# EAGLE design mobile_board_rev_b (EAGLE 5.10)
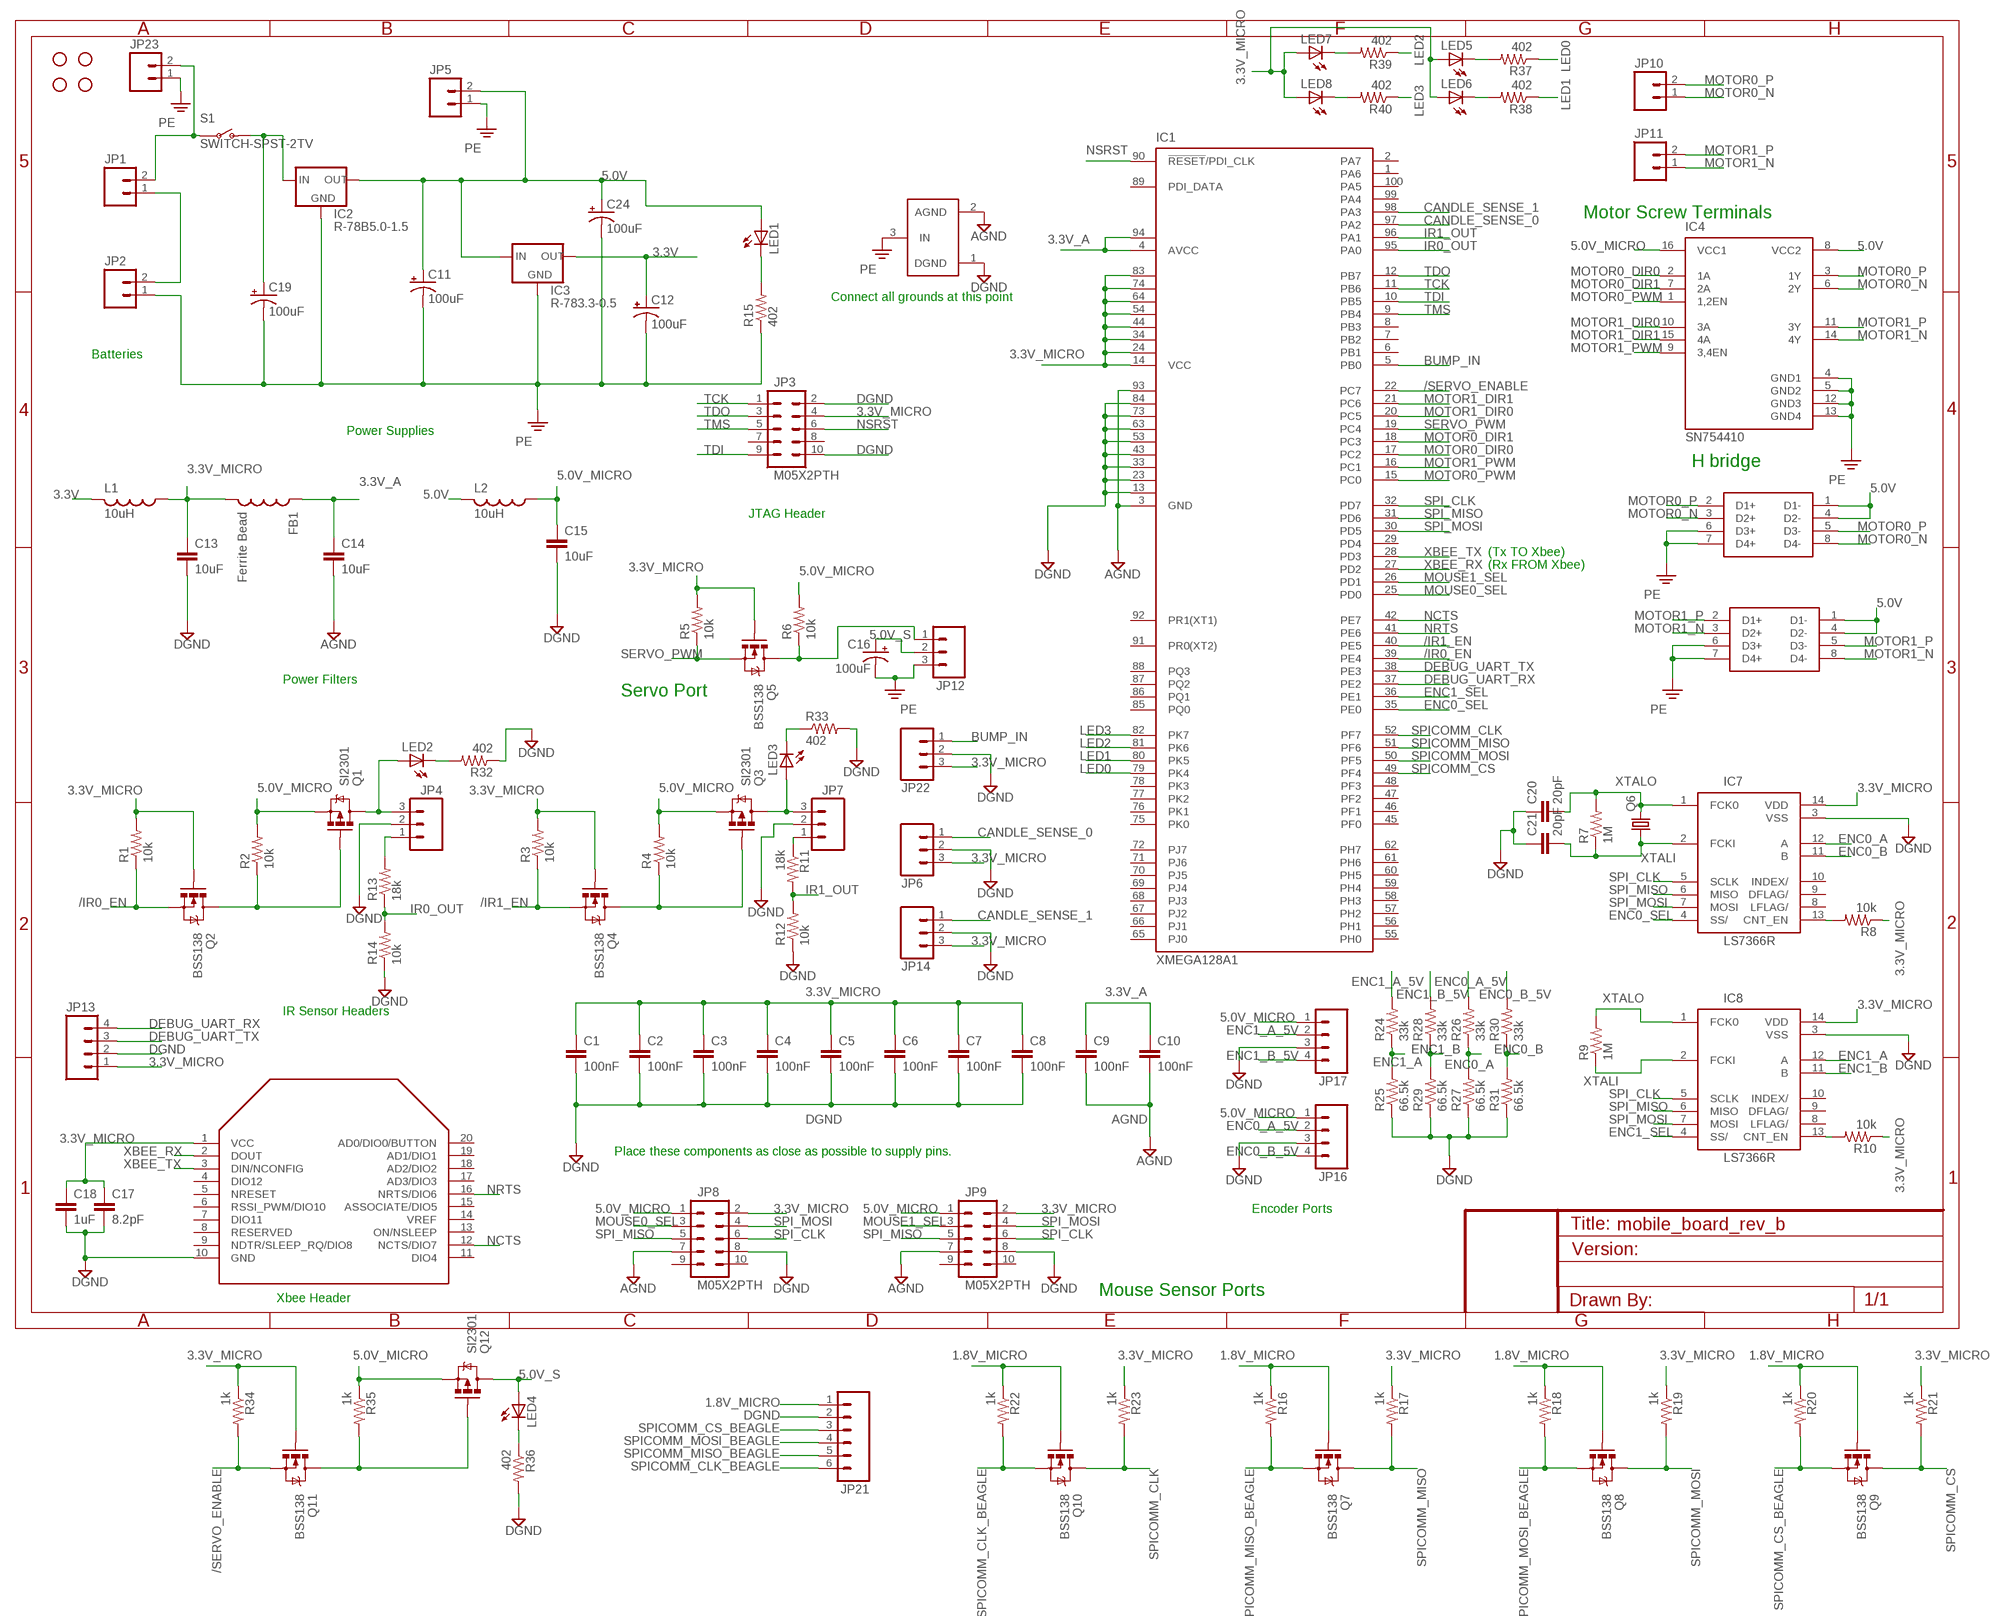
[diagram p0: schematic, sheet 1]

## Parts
C1  100nF  C-EUC0402  [C0402]
C2  100nF  C-EUC0402  [C0402]
C3  100nF  C-EUC0402  [C0402]
C4  100nF  C-EUC0402  [C0402]
C5  100nF  C-EUC0402  [C0402]
C6  100nF  C-EUC0402  [C0402]
C7  100nF  C-EUC0402  [C0402]
C8  100nF  C-EUC0402  [C0402]
C9  100nF  C-EUC0402  [C0402]
C10  100nF  C-EUC0402  [C0402]
C11  100uF  CPOL-USC  [PANASONIC_C]
C12  100uF  CPOL-USC  [PANASONIC_C]
C13  10uF  C-EUC1210  [C1210]
C14  10uF  C-EUC1210  [C1210]
C15  10uF  C-EUC1210  [C1210]
C16  100uF  CPOL-USC  [PANASONIC_C]
C17  8.2pF  C-EUC0805  [C0805]
C18  1uF  C-EUC0805  [C0805]
C19  100uF  CPOL-USC  [PANASONIC_C]
C20  20pF  C-EUC0402  [C0402]
C21  20pF  C-EUC0402  [C0402]
C24  100uF  CPOL-USC  [PANASONIC_C]
FB1  Ferrite Bead  INDUCTOR1210  [1210]
IC1  XMEGA128A1  [TQFP100]
IC2  R-78B5.0-1.5  78XXS  [78XXS]
IC3  R-783.3-0.5  78XXS  [78XXS]
IC4  SN754410  [16_DIP]
IC5  UC3611N  [8_DIP]
IC6  UC3611N  [8_DIP]
IC7  LS7366R  [SOIC_14]
IC8  LS7366R  [SOIC_14]
IC9  XBEE_ZIGBEE  [XBEE]
JP1  M02-JST-2MM-SMT  [S2B-PH]
JP2  M02-JST-2MM-SMT  [S2B-PH]
JP3  M05X2PTH  [AVR_ICSP]
JP4  M03PTH  [1X03]
JP5  M02-JST-2MM-SMT  [S2B-PH]
JP6  M03PTH  [1X03]
JP7  M03PTH  [1X03]
JP8  M05X2PTH  [AVR_ICSP]
JP9  M05X2PTH  [AVR_ICSP]
JP10  M02-JST-2MM-SMT  [S2B-PH]
JP11  M02-JST-2MM-SMT  [S2B-PH]
JP12  M03PTH  [1X03]
JP13  M04PTH  [1X04]
JP14  M03PTH  [1X03]
JP15  STAND-OFF  [STAND-OFF]
JP16  M04PTH  [1X04]
JP17  M04PTH  [1X04]
JP18  STAND-OFF  [STAND-OFF]
JP19  STAND-OFF  [STAND-OFF]
JP20  STAND-OFF  [STAND-OFF]
JP21  M06SIP  [1X06]
JP22  M03PTH  [1X03]
JP23  M02PTH  [1X02]
L1  10uH  L-USL1812  [L1812]
L2  10uH  L-USL1812  [L1812]
LED1  LED1206  [LED-1206]
LED2  LED1206  [LED-1206]
LED3  LED1206  [LED-1206]
LED4  LED1206  [LED-1206]
LED5  LED1206  [LED-1206]
LED6  LED1206  [LED-1206]
LED7  LED1206  [LED-1206]
LED8  LED1206  [LED-1206]
Q1  SI2301  MOSFET-PCHANNEL  [SOT23]
Q2  BSS138  MOSFET-NCHANNELSMD  [SOT23-3]
Q3  SI2301  MOSFET-PCHANNEL  [SOT23]
Q4  BSS138  MOSFET-NCHANNELSMD  [SOT23-3]
Q5  BSS138  MOSFET-NCHANNELSMD  [SOT23-3]
Q6  CRYSTALHC49US  [HC49US]
Q7  BSS138  MOSFET-NCHANNELSMD  [SOT23-3]
Q8  BSS138  MOSFET-NCHANNELSMD  [SOT23-3]
Q9  BSS138  MOSFET-NCHANNELSMD  [SOT23-3]
Q10  BSS138  MOSFET-NCHANNELSMD  [SOT23-3]
Q11  BSS138  MOSFET-NCHANNELSMD  [SOT23-3]
Q12  SI2301  MOSFET-PCHANNEL  [SOT23]
R1  10k  R-US_R0805  [R0805]
R2  10k  R-US_R0805  [R0805]
R3  10k  R-US_R0805  [R0805]
R4  10k  R-US_R0805  [R0805]
R5  10k  R-US_R0805  [R0805]
R6  10k  R-US_R0805  [R0805]
R7  1M  R-US_R0402  [R0402]
R8  10k  R-US_R0402  [R0402]
R9  1M  R-US_R0402  [R0402]
R10  10k  R-US_R0402  [R0402]
R11  18k  R-US_R0805  [R0805]
R12  10k  R-US_R0805  [R0805]
R13  18k  R-US_R0805  [R0805]
R14  10k  R-US_R0805  [R0805]
R15  402  R-US_R0805  [R0805]
R16  1k  R-US_R0402  [R0402]
R17  1k  R-US_R0402  [R0402]
R18  1k  R-US_R0402  [R0402]
R19  1k  R-US_R0402  [R0402]
R20  1k  R-US_R0402  [R0402]
R21  1k  R-US_R0402  [R0402]
R22  1k  R-US_R0402  [R0402]
R23  1k  R-US_R0402  [R0402]
R24  33k  R-US_R0402  [R0402]
R25  66.5k  R-US_R0402  [R0402]
R26  33k  R-US_R0402  [R0402]
R27  66.5k  R-US_R0402  [R0402]
R28  33k  R-US_R0402  [R0402]
R29  66.5k  R-US_R0402  [R0402]
R30  33k  R-US_R0402  [R0402]
R31  66.5k  R-US_R0402  [R0402]
R32  402  R-US_R0805  [R0805]
R33  402  R-US_R0805  [R0805]
R34  1k  R-US_R0402  [R0402]
R35  1k  R-US_R0402  [R0402]
R36  402  R-US_R0805  [R0805]
R37  402  R-US_R0805  [R0805]
R38  402  R-US_R0805  [R0805]
R39  402  R-US_R0805  [R0805]
R40  402  R-US_R0805  [R0805]
S1  SWITCH-SPST-2TV  [SWITCH-SPST-VERTICAL]
U$1  GND_CONNECT  [GND_CONNECT]

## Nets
1.8V_MICRO: JP21.1 Q7.1(G) Q8.1(G) Q9.1(G) Q10.1(G) R16.1 R18.1 R20.1 R22.1
3.3V: C12.+ IC3.OUT L1.2
3.3V_A: C9.1 C10.1 C14.1 FB1.1 IC1.4(AVCC) IC1.94(AVCC1)
3.3V_MICRO: C1.1 C2.1 C3.1 C4.1 C5.1 C6.1 C7.1 C8.1 C13.1 C17.1 C18.1 FB1.2 IC1.14(VCC) IC1.24(VCC1) IC1.34(VCC2) IC1.44(VCC3) IC1.54(VCC4) IC1.64(VCC5) IC1.74(VCC6) IC1.83(VCC7) IC7.14(VDD) IC8.14(VDD) IC9.1(VCC) JP3.4 JP6.3 JP8.2 JP9.2 JP13.1 JP14.3 JP22.3 L1.1 LED5.A LED6.A LED7.A LED8.A Q2.1(G) Q4.1(G) Q5.1(G) Q11.1(G) R1.2 R3.2 R5.2 R8.1 R10.1 R17.1 R19.1 R21.1 R23.1 R34.1
5.0V: C11.+ C24.+ IC2.OUT IC3.IN IC4.8(VCC2) IC5.1(D1-) IC5.4(D2-) IC6.1(D1-) IC6.4(D2-) JP5.2 L2.2 LED1.A
5.0V_MICRO: C15.1 IC4.16(VCC1) JP8.1 JP9.1 JP16.1 JP17.1 L2.1 Q1.2(S) Q3.2(S) Q12.2(S) R2.2 R4.2 R6.2 R35.1
5.0V_S: C16.+ JP12.2 LED4.A Q12.3(D)
/IR0_EN: IC1.39(PE4) Q2.2(S) R1.1
/IR1_EN: IC1.40(PE5) Q4.2(S) R3.1
/SERVO_ENABLE: IC1.22(PC7) Q11.2(S) R34.2
AGND: C9.2 C10.2 C14.2 IC1.3(GND) IC1.93(GND9) JP8.7 JP9.7 U$1.2(AGND)
BUMP_IN: IC1.5(PB0) JP22.1
CANDLE_SENSE_0: IC1.97(PA2) JP6.1
CANDLE_SENSE_1: IC1.98(PA3) JP14.1
DEBUG_UART_RX: IC1.37(PE2) JP13.4
DEBUG_UART_TX: IC1.38(PE3) JP13.3
DGND: C1.2 C2.2 C3.2 C4.2 C5.2 C6.2 C7.2 C8.2 C13.2 C15.2 C17.2 C18.2 C20.1 C21.1 IC1.13(GND1) IC1.23(GND2) IC1.33(GND3) IC1.43(GND4) IC1.53(GND5) IC1.63(GND6) IC1.73(GND7) IC1.84(GND8) IC7.3(VSS) IC8.3(VSS) IC9.10(GND) JP3.2 JP3.10 JP4.2 JP6.2 JP7.2 JP8.8 JP9.8 JP13.2 JP14.2 JP16.3 JP17.3 JP21.2 JP22.2 R12.1 R14.1 R25.1 R27.1 R29.1 R31.1 R32.1 R33.2 R36.2 U$1.1(DGND)
ENC0_A: IC7.12(A) R26.1 R27.2
ENC0_A_5V: JP16.2 R26.2
ENC0_B: IC7.11(B) R30.1 R31.2
ENC0_B_5V: JP16.4 R30.2
ENC0_SEL: IC1.35(PE0) IC7.4(SS/)
ENC1_A: IC8.12(A) R24.1 R25.2
ENC1_A_5V: JP17.2 R24.2
ENC1_B: IC8.11(B) R28.1 R29.2
ENC1_B_5V: JP17.4 R28.2
ENC1_SEL: IC1.36(PE1) IC8.4(SS/)
IR0_OUT: IC1.95(PA0) R13.1 R14.2
IR1_OUT: IC1.96(PA1) R11.2 R12.2
LED0: IC1.79(PK4) R37.1
LED1: IC1.80(PK5) R38.1
LED2: IC1.81(PK6) R39.1
LED3: IC1.82(PK7) R40.1
MOTOR0_DIR0: IC1.17(PC2) IC4.2(1A)
MOTOR0_DIR1: IC1.18(PC3) IC4.7(2A)
MOTOR0_N: IC4.6(2Y) IC5.3(D2+) IC5.8(D4-) JP10.1
MOTOR0_P: IC4.3(1Y) IC5.2(D1+) IC5.5(D3-) JP10.2
MOTOR0_PWM: IC1.15(PC0) IC4.1(1,2EN)
MOTOR1_DIR0: IC1.20(PC5) IC4.10(3A)
MOTOR1_DIR1: IC1.21(PC6) IC4.15(4A)
MOTOR1_N: IC4.14(4Y) IC6.3(D2+) IC6.8(D4-) JP11.1
MOTOR1_P: IC4.11(3Y) IC6.2(D1+) IC6.5(D3-) JP11.2
MOTOR1_PWM: IC1.16(PC1) IC4.9(3,4EN)
MOUSE0_SEL: IC1.25(PD0) JP8.3
MOUSE1_SEL: IC1.26(PD1) JP9.3
N$1: JP1.1 JP2.2
N$2: C19.+ IC2.IN S1.1(O)
N$3: LED1.C R15.2
N$4: JP7.3 LED3.A Q3.3(D)
N$5: Q3.1(G) Q4.3(D) R4.1
N$6: LED2.C R32.2
N$7: JP1.2 JP23.2 S1.2(P)
N$8: JP4.3 LED2.A Q1.3(D)
N$9: Q1.1(G) Q2.3(D) R2.1
N$10: LED3.C R33.1
N$11: JP12.1 Q5.3(D) R6.1
N$12: IC7.13(CNT_EN) R8.2
N$13: LED4.C R36.1
N$14: Q11.3(D) Q12.1(G) R35.2
N$15: IC8.13(CNT_EN) R10.2
N$16: JP7.1 R11.1
N$18: JP4.1 R13.2
N$20: LED8.C R40.2
N$21: LED7.C R39.2
N$22: LED5.C R37.2
N$23: LED6.C R38.2
NCTS: IC1.42(PE7) IC9.12(NCTS/DIO7)
NRTS: IC1.41(PE6) IC9.16(NRTS/DIO6)
NSRST: IC1.90(!RESET!/PDI_CLK) JP3.6
PE: C11.- C12.- C16.- C19.- C24.- IC2.GND IC3.GND IC4.4(GND1) IC4.5(GND2) IC4.12(GND3) IC4.13(GND4) IC5.6(D3+) IC5.7(D4+) IC6.6(D3+) IC6.7(D4+) JP2.1 JP5.1 JP12.3 JP23.1 R15.1 U$1.3(IN)
SERVO_PWM: IC1.19(PC4) Q5.2(S) R5.1
SPI_CLK: IC1.32(PD7) IC7.5(SCLK) IC8.5(SCLK) JP8.6 JP9.6
SPI_MISO: IC1.31(PD6) IC7.6(MISO) IC8.6(MISO) JP8.5 JP9.5
SPI_MOSI: IC1.30(PD5) IC7.7(MOSI) IC8.7(MOSI) JP8.4 JP9.4
SPICOMM_CLK: IC1.52(PF7) Q10.3(D) R23.2
SPICOMM_CLK_BEAGLE: JP21.6 Q10.2(S) R22.2
SPICOMM_CS: IC1.49(PF4) Q9.3(D) R21.2
SPICOMM_CS_BEAGLE: JP21.3 Q9.2(S) R20.2
SPICOMM_MISO: IC1.51(PF6) Q7.3(D) R17.2
SPICOMM_MISO_BEAGLE: JP21.5 Q7.2(S) R16.2
SPICOMM_MOSI: IC1.50(PF5) Q8.3(D) R19.2
SPICOMM_MOSI_BEAGLE: JP21.4 Q8.2(S) R18.2
TCK: IC1.11(PB6) JP3.1
TDI: IC1.10(PB5) JP3.9
TDO: IC1.12(PB7) JP3.3
TMS: IC1.9(PB4) JP3.5
XBEE_RX: IC1.27(PD2) IC9.2(DOUT)
XBEE_TX: IC1.28(PD3) IC9.3(DIN/NCONFIG)
XTALI: C21.2 IC7.2(FCKI) IC8.2(FCKI) Q6.1 R7.1 R9.1
XTALO: C20.2 IC7.1(FCK0) IC8.1(FCK0) Q6.2 R7.2 R9.2
Unconnected: IC1.1(PA6) IC1.2(PA7) IC1.6(PB1) IC1.7(PB2) IC1.8(PB3) IC1.29(PD4) IC1.45(PF0) IC1.46(PF1) IC1.47(PF2) IC1.48(PF3) IC1.55(PH0) IC1.56(PH1) IC1.57(PH2) IC1.58(PH3) IC1.59(PH4) IC1.60(PH5) IC1.61(PH6) IC1.62(PH7) IC1.65(PJ0) IC1.66(PJ1) IC1.67(PJ2) IC1.68(PJ3) IC1.69(PJ4) IC1.70(PJ5) IC1.71(PJ6) IC1.72(PJ7) IC1.75(PK0) IC1.76(PK1) IC1.77(PK2) IC1.78(PK3) IC1.85(PQ0) IC1.86(PQ1) IC1.87(PQ2) IC1.88(PQ3) IC1.89(PDI_DATA) IC1.91(PR0(XT2)) IC1.92(PR1(XT1)) IC1.99(PA4) IC1.100(PA5) IC7.8(LFLAG/) IC7.9(DFLAG/) IC7.10(INDEX/) IC8.8(LFLAG/) IC8.9(DFLAG/) IC8.10(INDEX/) IC9.4(DIO12) IC9.5(NRESET) IC9.6(RSSI_PWM/DIO10) IC9.7(DIO11) IC9.8(RESERVED) IC9.9(NDTR/SLEEP_RQ/DIO8) IC9.11(DIO4) IC9.13(ON/NSLEEP) IC9.14(VREF) IC9.15(ASSOCIATE/DIO5) IC9.17(AD3/DIO3) IC9.18(AD2/DIO2) IC9.19(AD1/DIO1) IC9.20(AD0/DIO0/BUTTON) JP3.7 JP3.8 JP8.9 JP8.10 JP9.9 JP9.10

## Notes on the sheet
- Motor Screw Terminals
- Connect all grounds at this point
- Batteries
- Power Supplies
- H bridge
- JTAG Header
- (Tx TO Xbee)
- (Rx FROM Xbee)
- Power Filters
- Servo Port
- IR Sensor Headers
- Place these components as close as possible to supply pins.
- Encoder Ports
- Mouse Sensor Ports
- Xbee Header

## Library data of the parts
C1-C10 C13-C15 C17 C18 C20 C21 = resistor:C-EU: CAPACITOR, European symbol
C11 C12 C16 C19 C24 = resistor:CPOL-US: POLARIZED CAPACITOR, American symbol
FB1 = SparkFun:INDUCTOR: Inductors
IC1 = atmel:XMEGA128A1: MICROCONTROLLER Features High-performance, Low-power 8/16-bit AVR XMEGA Microcontroller Non-Volatile Program and Data Memories - 64K - 384K Bytes of In-System Self-Programmable Flash - 4K - 8K Bytes Boot Section with Independent Lock Bits - 2 KB - 4 KB EEPROM - 4 KB - 32 KB Internal SRAM External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
IC2 IC3 = v-reg:78XXS: VOLTAGE REGULATOR
IC4 = e_jones_custom:SN754410: Quad Half Bridge Motor Driver
IC5 IC6 = e_jones_custom:UC3611N
IC7 IC8 = e_jones_custom:LS7366R: Quadrature encoder counter IC with SPI interface.
IC9 = e_jones_custom:XBEE_ZIGBEE
JP1 JP2 JP5 JP10 JP11 JP23 = SparkFun:M02: Header 2
JP3 JP8 JP9 = SparkFun:M05X2: Header 5x2 Standard 10-pin dual row 0.1" header. Commonly used with AVR-ISP. Use with Spark Fun Electronics SKU: PRT-00778
JP4 JP6 JP7 JP12 JP14 JP22 = SparkFun:M03: Header 3 Standard 3-pin 0.1" header. Use with straight break away headers (SKU : PRT-00116), right angle break away headers (PRT-00553), swiss pins (PRT-00743), machine pins (PRT-00117), and female headers (PRT-00115). Molex polarized connector foot print use with SKU : PRT-08232 with associated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
JP13 JP16 JP17 = SparkFun:M04: Header 4 Standard 4-pin 0.1" header. Use with straight break away headers (SKU : PRT-00116), right angle break away headers (PRT-00553), swiss pins (PRT-00743), machine pins (PRT-00117), and female headers (PRT-00115). Molex polarized connector foot print use with SKU : PRT-08231 with associated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
JP15 JP18-JP20 = SparkFun:STAND-OFF: Stand Off
JP21 = SparkFun:M06: Header 6 Standard 6-pin 0.1" header. Use with straight break away headers (SKU : PRT-00116), right angle break away headers (PRT-00553), swiss pins (PRT-00743), machine pins (PRT-00117), and female headers (PRT-00115). Molex polarized connector foot print use with SKU : PRT-08094 with associated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
L1 L2 = resistor:L-US: INDUCTOR, American symbol
LED1-LED8 = SparkFun:LED: LEDs
Q1 Q3 Q12 = SparkFun:MOSFET-PCHANNEL
Q2 Q4 Q5 Q7-Q11 = SparkFun:MOSFET-NCHANNEL
Q6 = SparkFun:CRYSTAL: Crystals
R1-R40 = resistor:R-US_: RESISTOR, American symbol
S1 = SparkFun:SWITCH-SPST-2
U$1 = SparkFun:GND_CONNECT

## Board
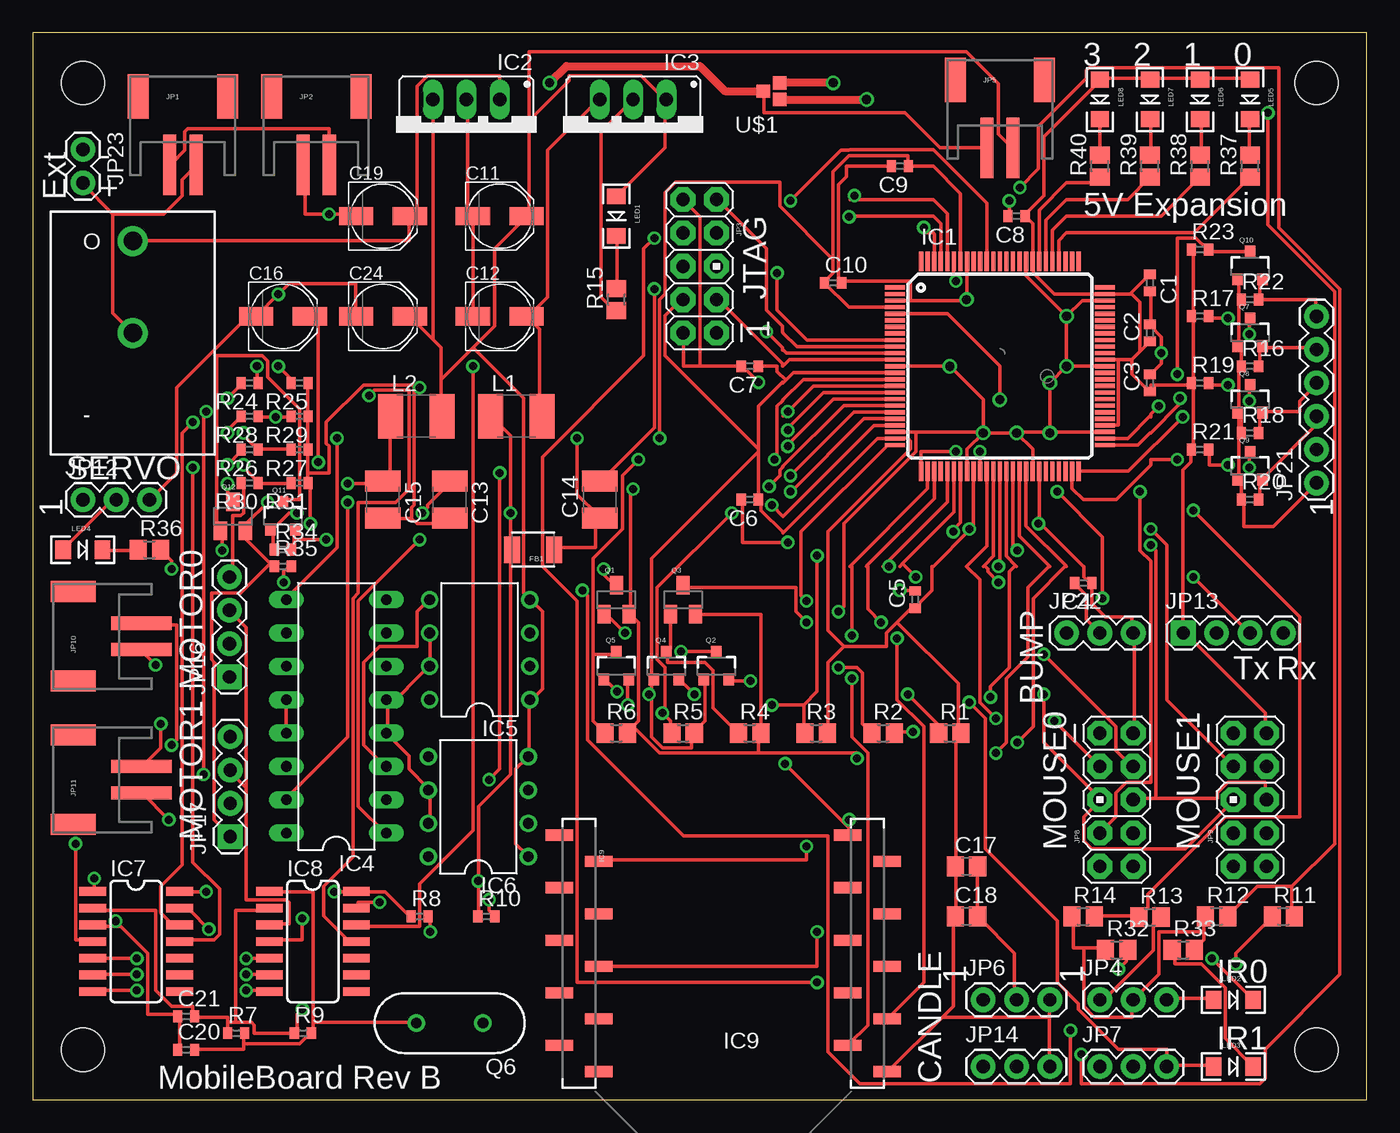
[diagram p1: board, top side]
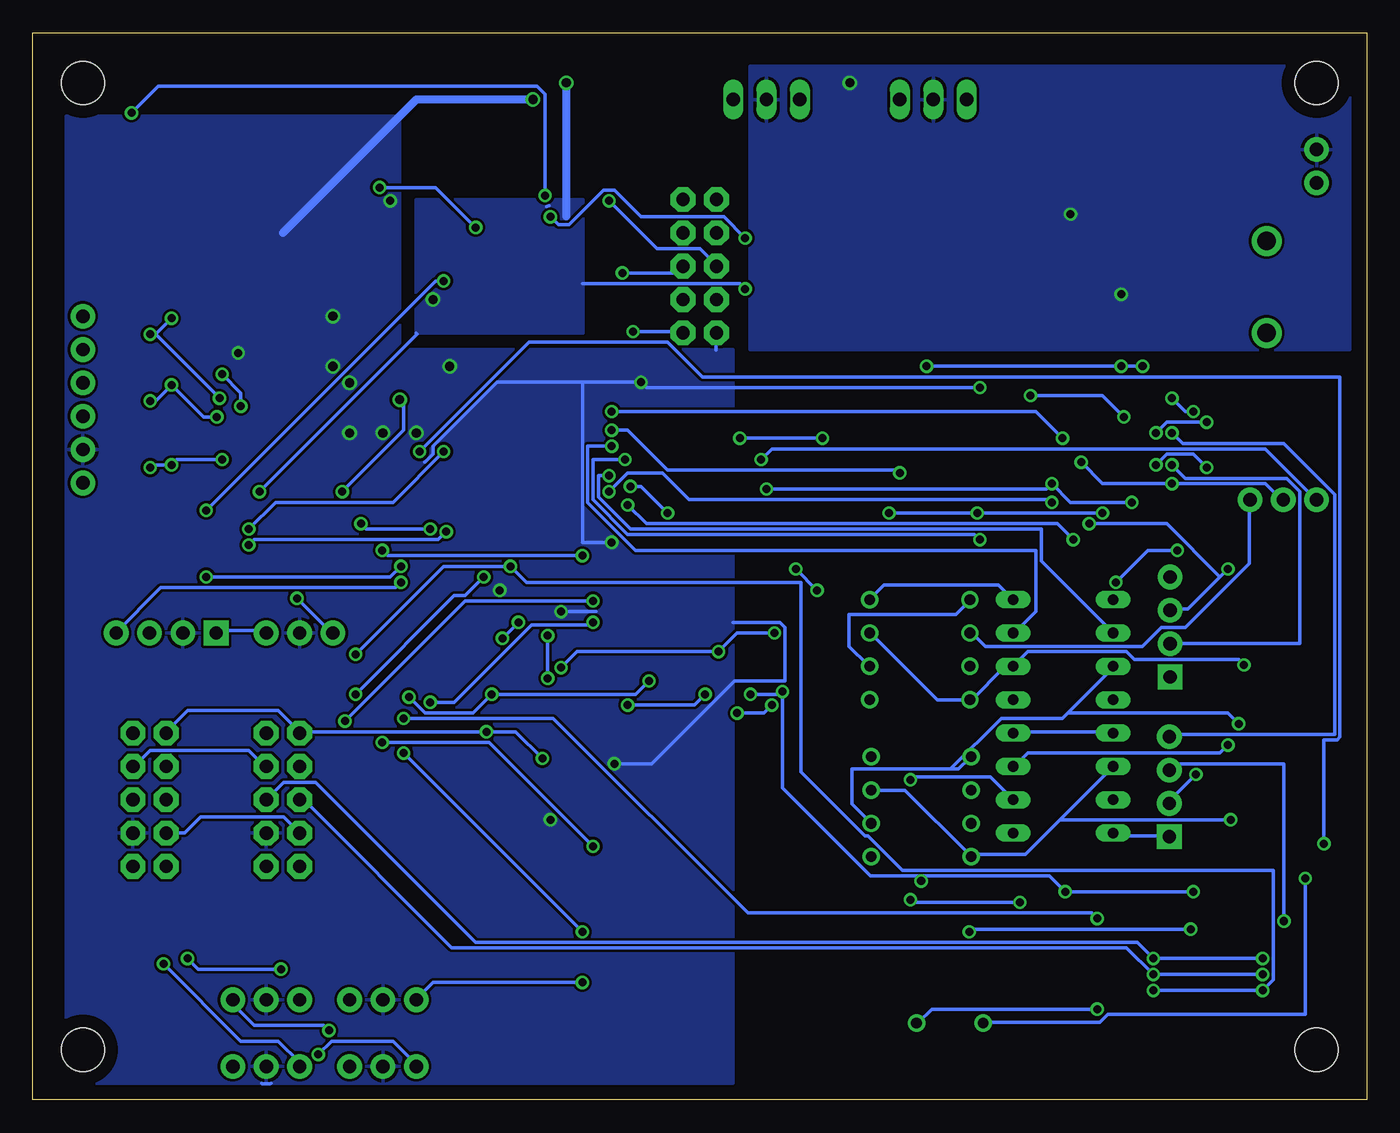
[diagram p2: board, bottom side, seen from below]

Size 101.6 x 81.28 mm. Coordinates in mm from the lower left corner, seen from the top.
Outline: 0,0 101.6,0 101.6,81.28 0,81.28 0,0
Copper layers (1*16): Top 0.035mm / dielectric 1.5mm / Bottom 0.035mm
Design rules "default *": minimum track width 10mil, minimum drill 24mil, track to track 6mil, track to pad 6mil, pad to pad 6mil, via to via 6mil, smd to smd 6mil, copper to edge 40mil, drill to drill 8mil, minimum pad ring 10mil, minimum via ring 8mil, stop-mask expansion 4mil, vias tented up to drill 0mil, thermal gap 10mil

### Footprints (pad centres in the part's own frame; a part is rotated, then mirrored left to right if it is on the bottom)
C0402 = smd 0.7 x 0.9: 1 -0.65,0; 2 0.65,0
PANASONIC_C = smd 2.6 x 1.4: + 2.05,0; - -2.05,0
C1210 = smd 1.6 x 2.7: 1 -1.4,0; 2 1.4,0
C0805 = smd 1.3 x 1.5: 1 -0.85,0; 2 0.85,0
1210 = smd 1.2 x 2: 1 -1.6,0; 2 1.6,0
TQFP100 = smd 1.5 x 0.325: 1 -8,6; 2 -8,5.5; 3 -8,5; 4 -8,4.5; 5 -8,4; 6 -8,3.5; 7 -8,3; 8 -8,2.5; 9 -8,2; 10 -8,1.5; 11 -8,1; 12 -8,0.5; 13 -8,0; 14 -8,-0.5; 15 -8,-1; 16 -8,-1.5; 17 -8,-2; 18 -8,-2.5; 19 -8,-3; 20 -8,-3.5; 21 -8,-4; 22 -8,-4.5; 23 -8,-5; 24 -8,-5.5; 25 -8,-6; 51 8,-6; 52 8,-5.5; 53 8,-5; 54 8,-4.5; 55 8,-4; 56 8,-3.5; 57 8,-3; 58 8,-2.5; 59 8,-2; 60 8,-1.5; 61 8,-1; 62 8,-0.5; 63 8,0; 64 8,0.5; 65 8,1; 66 8,1.5; 67 8,2; 68 8,2.5; 69 8,3; 70 8,3.5; 71 8,4; 72 8,4.5; 73 8,5; 74 8,5.5; 75 8,6 | smd 0.325 x 1.5: 26 -6,-8; 27 -5.5,-8; 28 -5,-8; 29 -4.5,-8; 30 -4,-8; 31 -3.5,-8; 32 -3,-8; 33 -2.5,-8; 34 -2,-8; 35 -1.5,-8; 36 -1,-8; 37 -0.5,-8; 38 0,-8; 39 0.5,-8; 40 1,-8; 41 1.5,-8; 42 2,-8; 43 2.5,-8; 44 3,-8; 45 3.5,-8; 46 4,-8; 47 4.5,-8; 48 5,-8; 49 5.5,-8; 50 6,-8; 76 6,8; 77 5.5,8; 78 5,8; 79 4.5,8; 80 4,8; 81 3.5,8; 82 3,8; 83 2.5,8; 84 2,8; 85 1.5,8; 86 1,8; 87 0.5,8; 88 0,8; 89 -0.5,8; 90 -1,8; 91 -1.5,8; 92 -2,8; 93 -2.5,8; 94 -3,8; 95 -3.5,8; 96 -4,8; 97 -4.5,8; 98 -5,8; 99 -5.5,8; 100 -6,8
78XXS = drill 1.016 long: GND 0,-2.54; IN -2.54,-2.54; OUT 2.54,-2.54
16_DIP = drill 0.813 long: 1 -8.89,-3.81; 2 -6.35,-3.81; 3 -3.81,-3.81; 4 -1.27,-3.81; 5 1.27,-3.81; 6 3.81,-3.81; 7 6.35,-3.81; 8 8.89,-3.81; 9 8.89,3.81; 10 6.35,3.81; 11 3.81,3.81; 12 1.27,3.81; 13 -1.27,3.81; 14 -3.81,3.81; 15 -6.35,3.81; 16 -8.89,3.81
8_DIP = drill 0.813 pad 1.27 round: 1 -3.81,-3.81; 2 -1.27,-3.81; 3 1.27,-3.81; 4 3.81,-3.81; 5 3.81,3.81; 6 1.27,3.81; 7 -1.27,3.81; 8 -3.81,3.81
SOIC_14 = smd 0.66 x 2.032: 1 -3.175,-3.315; 2 -1.905,-3.315; 3 -0.635,-3.315; 4 0.635,-3.315; 5 1.905,-3.315; 6 3.175,-3.315; 7 4.445,-3.315; 8 4.445,3.315; 9 3.175,3.315; 10 1.905,3.315; 11 0.635,3.315; 12 -0.635,3.315; 13 -1.905,3.315; 14 -3.175,3.315
XBEE = smd 0.85 x 2.1: 1 -8,-11.73; 2 -6,-8.73; 3 -4,-11.73; 4 -2,-8.73; 5 0,-11.73; 6 2,-8.73; 7 4,-11.73; 8 6,-8.73; 9 8,-11.73; 10 10,-8.73; 11 10,13.23; 12 8,10.23; 13 6,13.23; 14 4,10.23; 15 2,13.23; 16 0,10.23; 17 -2,13.23; 18 -4,10.23; 19 -6,13.23; 20 -8,10.23
S2B-PH = smd 1 x 4.6: 1 -1,-3.7; 2 1,-3.7 | smd 1.6 x 3.4: NC1 -3.4,1.5; NC2 3.4,1.5
AVR_ICSP = drill 1.016 pad 1.88 octagon: 1 -1.27,5.08; 2 1.27,5.08; 3 -1.27,2.54; 4 1.27,2.54; 5 -1.27,0; 6 1.27,0; 7 -1.27,-2.54; 8 1.27,-2.54; 9 -1.27,-5.08; 10 1.27,-5.08
1X03 = drill 1.016 pad 1.88 round: 1 0,0; 2 2.54,0; 3 5.08,0
1X04 = drill 1.016 pad 1.88 square: 1 0,0 | drill 1.016 pad 1.88 round: 2 2.54,0; 3 5.08,0; 4 7.62,0
STAND-OFF = hole 3.302: 0,0
1X06 = drill 1.016 pad 1.88 round: 1 0,0; 2 2.54,0; 3 5.08,0; 4 7.62,0; 5 10.16,0; 6 12.7,0
1X02 = drill 1.016 pad 1.88 round: 1 0,0; 2 2.54,0
L1812 = smd 1.9 x 3.4: 1 -1.95,0; 2 1.95,0
LED-1206 = smd 1.2 x 1.4: A -1.5,0; C 1.5,0
SOT23 = smd 1 x 1.4: 1 -0.95,-1.1; 2 0.95,-1.1; 3 0,1.1
SOT23-3 = smd 0.8 x 0.9: 1 -0.95,-1; 2 0.95,-1; 3 0,1.1
HC49US = drill 0.813 round: 1 -2.54,0; 2 2.54,0
R0805 = smd 1.3 x 1.5: 1 -0.85,0; 2 0.85,0
R0402 = smd 0.7 x 0.9: 1 -0.65,0; 2 0.65,0
SWITCH-SPST-VERTICAL = drill 1.4 pad 2.286 round: 1 0,7; 2 0,0
GND_CONNECT = smd 1.016 x 1.016: 1 -1.016,0; 2 -1.016,-1.27; 3 0.254,-0.635

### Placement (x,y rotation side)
C1  85.09,62.23 270 top
C2  85.09,58.42 90 top
C3  85.09,54.61 90 top
C4  80.01,39.37 180 top
C5  67.21,38.1 90 top
C6  54.61,45.72 180 top
C7  54.61,55.88 180 top
C8  74.93,67.31 180 top
C9  66.04,71.12 180 top
C10  60.96,62.23 0 top
C11  35.56,67.31 0 top
C12  35.56,59.69 0 top
C13  31.75,45.72 270 top
C14  43.18,45.72 90 top
C15  26.67,45.72 270 top
C16  19.05,59.69 0 top
C17  71.12,17.78 0 top
C18  71.12,13.97 0 top
C19  26.67,67.31 0 top
C20  11.68,3.81 0 top
C21  11.68,6.35 0 top
C24  26.67,59.69 0 top
FB1  38.1,41.91 180 top
IC1  73.66,55.88 0 top
IC2  33.02,73.66 180 top
IC3  45.72,73.66 180 top
IC4  23.11,29.21 90 top
IC5  34.04,34.29 90 top
IC6  33.93,22.33 90 top
IC7  7.87,12.7 270 top
IC8  21.34,12.7 270 top
IC9  53.34,10.16 90 top
JP1  11.43,74.93 0 top
JP2  21.59,74.93 0 top
JP3  50.8,63.5 180 top
JP4  81.28,7.62 0 top
JP5  73.66,76.2 0 top
JP6  72.39,7.62 0 top
JP7  81.28,2.54 0 top
JP8  82.55,22.86 0 top
JP9  92.71,22.86 0 top
JP10  4.57,35.31 90 top
JP11  4.57,24.38 90 top
JP12  3.81,45.72 0 top
JP13  87.63,35.56 0 top
JP14  72.39,2.54 0 top
JP15  97.79,77.47 0 top
JP16  14.99,32.21 90 top
JP17  15.04,20.04 90 top
JP18  97.79,3.81 0 top
JP19  3.81,77.47 0 top
JP20  3.81,3.81 0 top
JP21  97.79,46.99 90 top
JP22  78.74,35.56 0 top
JP23  3.81,72.39 270 top
L1  36.83,52.07 0 top
L2  29.21,52.07 0 top
LED1  44.45,67.31 270 top
LED2  91.44,7.62 0 top
LED3  91.44,2.54 0 top
LED4  3.81,41.91 0 top
LED5  92.71,76.2 270 top
LED6  88.9,76.2 270 top
LED7  85.09,76.2 270 top
LED8  81.28,76.2 270 top
Q1  44.45,38.1 0 top
Q2  52.07,33.02 0 top
Q3  49.53,38.1 0 top
Q4  48.26,33.02 0 top
Q5  44.45,33.02 0 top
Q6  31.75,5.84 180 top
Q7  92.71,58.42 0 top
Q8  92.71,53.34 0 top
Q9  92.71,48.26 0 top
Q10  92.71,63.5 0 top
Q11  19.05,44.45 0 top
Q12  15.24,44.45 0 top
R1  69.85,27.94 0 top
R2  64.77,27.94 0 top
R3  59.66,27.94 0 top
R4  54.61,27.94 0 top
R5  49.53,27.94 0 top
R6  44.45,27.94 0 top
R7  15.49,5.08 0 top
R8  29.46,13.97 0 top
R9  20.57,5.08 0 top
R10  34.54,13.97 0 top
R11  95.25,13.97 0 top
R12  90.17,13.97 0 top
R13  85.09,13.92 0 top
R14  80.01,13.97 0 top
R15  44.45,60.96 90 top
R16  92.71,55.88 0 top
R17  88.9,59.69 0 top
R18  92.71,50.8 0 top
R19  88.9,54.61 0 top
R20  92.71,45.72 0 top
R21  88.9,49.53 0 top
R22  92.71,60.96 0 top
R23  88.9,64.77 0 top
R24  16.51,54.61 180 top
R25  20.32,54.61 180 top
R26  16.51,49.53 180 top
R27  20.32,49.53 180 top
R28  16.51,52.07 180 top
R29  20.32,52.07 180 top
R30  16.51,46.99 180 top
R31  20.32,46.99 180 top
R32  82.55,11.43 0 top
R33  87.63,11.43 0 top
R34  19.05,41.91 0 top
R35  19.05,40.64 0 top
R36  8.89,41.91 0 top
R37  92.71,71.12 90 top
R38  88.9,71.12 90 top
R39  85.09,71.12 90 top
R40  81.28,71.12 90 top
S1  7.62,58.42 0 top
U$1  55.88,76.2 180 top

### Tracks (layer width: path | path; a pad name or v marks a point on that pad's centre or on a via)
1.8V_MICRO
  Top 0.254: R22.1 91.85,61.16 91.85,62.38 Q10.1 | R16.1 92.05,57.1 91.85,57.3 Q7.1 91.85,57.51 91.85,60.76 R22.1 | 91.85,52.22 92.05,52.02 R18.1 | 91.85,52.22 91.85,47.35 Q9.1 91.85,47.14 92.05,46.94 R20.1 92.25,45.72 92.25,43.69 94.49,43.69 JP21.1 | 91.85,52.22 Q8.1 91.85,52.43 91.85,55.68 R16.1 | R16.1 | R22.1
3.3V
  Top 0.254: L1.2 38.61,52.22 38.61,58.73 37.8,59.54 C12.+ 37.8,59.74 39.22,61.16 39.22,72.34 43.08,76.2 IC3.OUT
3.3V_A  (via drill 0.61)
  Top 0.254: IC1.94 70.66,69.04 68.58,71.12 C9.1 66.65,71.12 66.65,71.93 62.18,71.93 60.96,70.71 60.96,64.01 | IC1.4 62.16,60.38 C10.1 60.35,62.38 60.96,62.99 60.96,64.01 | FB1.1 39.83,42.06 42.88,42.06 42.88,44.09 43.08,44.3 C14.1 43.08,44.5 41.45,46.13 v41.45,50.39 | v47.75,50.39 47.75,60.96 48.16,61.37 48.16,69.09 48.97,69.9 56.9,69.9 56.9,68.07 60.96,64.01
  Bottom 0.254: v41.45,50.39 v47.75,50.39
3.3V_MICRO  (via drill 0.61)
  Top 0.254: IC1.44 76.66,43.99 76.68,43.97 | 76.68,43.97 80.01,40.64 80.06,40.64 80.06,39.83 80.47,39.42 C4.1 80.67,39.22 80.67,37.8 81.69,36.78 83.72,36.78 83.72,35.56 JP22.3 83.92,35.56 83.92,28.04 JP8.2 | 82.7,56.38 IC1.64 | 83.7,56.38 82.7,56.38 | 83.7,56.38 84.37,57.05 | 84.37,57.05 C2.1 | 83.65,61.44 83.59,61.38 IC1.74 81.48,61.37 77.83,61.37 76.2,62.99 76.2,63.8 IC1.83 76.16,66.73 C8.1 75.59,67.46 77.01,68.89 77.01,73.36 81.28,77.62 LED8.A 81.28,77.83 84.94,77.83 LED7.A 85.14,77.83 88.8,77.83 LED6.A 89,77.83 92.66,77.83 LED5.A | 83.65,61.44 C1.1 | IC1.34 71.66,43.72 71.37,43.43 | 71.37,43.43 68.58,40.64 68.48,40.64 68.48,38.81 67.26,37.59 C5.1 67.06,37.59 65.84,36.37 | IC1.14 57.92,55.38 57.35,54.81 | 57.35,54.81 57.15,54.61 57.1,54.66 55.27,52.83 55.27,49.58 | 57.17,43.2 57.15,43.18 | 57.17,43.2 64.35,50.38 IC1.24 65.84,50.39 66.65,50.39 66.85,50.19 66.85,49.58 60.55,43.28 60.55,35.76 61.77,34.54 | JP9.2 93.88,28.04 93.88,29.46 87.78,35.56 JP13.1 87.58,35.56 87.58,47.95 88.19,48.56 88.19,49.38 R21.1 88.39,49.58 88.39,54.46 R19.1 | R23.1 88.39,64.62 88.39,59.74 R17.1 88.39,59.54 88.39,54.66 R19.1 | 83.7,56.38 83.72,56.29 83.72,55.27 84.94,54.05 C3.1 85.14,54.05 85.14,54.46 88.19,54.46 R19.1 | IC1.54 81.69,51.41 82.7,51.41 82.7,56.38 | 83.65,61.44 84.33,60.76 84.33,57.1 84.37,57.05 | 61.77,34.54 60.55,33.33 60.55,28.04 R3.2 | 61.77,34.54 65.02,34.54 65.02,35.56 65.84,36.37 | 77.42,6.3 77.42,7.52 JP6.3 | 77.42,6.3 77.42,2.64 JP14.3 | 69.29,6.3 70.1,7.11 70.1,13.82 C18.1 70.31,14.02 70.31,17.68 C17.1 70.31,17.88 70.31,27.64 70.51,27.84 R1.2 70.51,28.04 70.51,31.7 65.84,36.37
  Top 0.254: 69.29,6.3 65.23,2.23 IC9.1 | 69.29,6.3 77.42,6.3 | R34.1 18.29,42.06 18.29,43.28 Q11.1 18.29,43.48 19.51,44.7 v20.12,44.7 | v29.67,44.7 30.07,45.11 30.07,45.31 31.7,46.94 C13.1 | R10.1 33.93,14.02 v33.93,16.66 33.93,22.35 36.37,24.79 36.37,41.86 FB1.2 36.37,42.06 v36.37,44.7 36.37,50.6 34.95,52.02 L1.1 | R8.1 28.65,14.02 26.82,15.85 24.79,15.85 IC8.14 24.59,15.85 v22.96,15.85 | v13.21,15.85 11.38,15.85 IC7.14 | v44.5,31.09 43.69,31.9 Q5.1 | Q2.1 51.21,31.9 51.21,28.85 50.39,28.04 R5.2 50.19,27.84 50.19,26.82 47.95,26.82 47.14,27.64 47.14,30.68 v46.94,30.89 47.14,31.09 47.14,31.9 Q4.1 47.14,32.11 47.14,41.25 55.27,49.38 | C7.1 56.69,55.88 56.69,55.47 57.35,54.81 | C6.1 55.47,45.52 55.47,44.91 57.17,43.2 | 55.27,49.38 C6.1 | 55.27,49.38 55.27,49.58 | C6.1 | 55.27,49.58 48.16,56.69 48.16,59.74 49.38,60.96 JP3.4 | v76.61,43.89 76.68,43.97 | 71.37,43.43 v71.32,43.48
  Bottom 0.254: JP22.3 83.92,35.56 84.12,35.76 87.38,35.76 87.58,35.56 JP13.1 | v20.12,44.7 v29.67,44.7 v36.37,44.7 | v13.21,15.85 v22.96,15.85 24.18,17.07 33.93,17.07 | v46.94,30.89 44.7,30.89 v44.5,31.09 44.5,23.77 37.8,17.07 33.93,17.07 | 33.93,17.07 v33.93,16.66 | v76.61,43.89 76.2,43.48 v71.32,43.48
5.0V
  Top 0.254: IC6.1 37.59,18.69 36.78,19.51 36.78,25.2 37.59,26.01 IC6.4 37.8,26.21 37.8,30.48 IC5.1 38,30.48 38.81,31.29 38.81,37.19 38,38 IC5.4 37.8,38.2 37.39,38.61 37.39,53.44 33.53,57.3 | 48.16,76.2 48.16,72.54 44.5,68.89 LED1.A | 30.48,57.91 31.09,57.3 31.09,54.86 | 30.48,57.91 28.85,59.54 C24.+ | 31.09,54.86 31.09,52.22 L2.2 | 33.53,57.3 31.09,54.86 | 33.53,57.3 35.15,58.93 35.15,64.82 37.59,67.26 C11.+ 37.8,67.46 37.8,74.57 | 30.48,57.91 IC2.OUT | 37.8,74.57 37.8,79.86 71.12,79.86 73.56,77.42 73.56,73.56 74.57,72.54 JP5.2 | 48.16,76.2 46.33,78.03 40.84,78.03 40.84,77.62 37.8,74.57 | 48.16,76.2 IC3.IN
  Bottom 0.254: IC4.8 28.04,39.22 36.78,39.22 37.8,38.2 IC5.4
5.0V_MICRO  (via drill 0.61)
  Top 0.254: L2.1 27.23,52.02 27.23,47.55 26.82,47.14 C15.1 26.62,46.94 v23.98,46.94 | 18.09,40.84 16.26,42.67 16.26,43.28 Q12.2 16.26,43.48 16.26,43.89 v17.88,45.52 | 18.09,40.84 18.29,40.64 R35.1 18.09,40.84 | 18.09,40.84 15.85,38.61 13.61,38.61 13.61,33.53 13.82,33.33 | 13.82,33.33 14.83,32.31 JP16.1 | 13.82,33.33 13.82,21.34 15.04,20.12 JP17.1 | 45.72,28.45 45.31,28.04 R6.2 45.72,28.45 | 45.72,28.45 46.13,28.85 46.13,36.37 45.52,36.98 Q1.2 45.52,37.19 45.52,46.33 v45.72,46.53 | Q3.2 50.6,36.98 55.47,36.98 55.47,28.04 R4.2 55.27,27.84 55.27,26.42 | 45.72,28.45 47.75,26.42 55.27,26.42 | v67.06,28.04 65.63,28.04 R2.2 | 55.27,26.42 62.79,26.42 v62.79,26.01
  Bottom 0.254: IC4.16 19.1,20.12 15.04,20.12 JP17.1 | v17.88,45.52 22.55,45.52 v23.98,46.94 24.38,46.53 v45.72,46.53 | 81.28,28.04 v67.06,28.04 64.82,28.04 v62.79,26.01 | 81.28,28.04 82.91,29.67 89.81,29.67 91.44,28.04 JP9.1 | 81.28,28.04 JP8.1
5.0V_S  (via drill 0.61)
  Top 0.254: LED4.A 2.44,42.06 6.1,45.72 JP12.2 | v14.83,46.94 14.83,46.13 15.24,45.72 Q12.3 | v21.74,48.56 21.74,58.93 21.13,59.54 C16.+
  Bottom 0.254: JP12.2 6.5,45.72 7.72,46.94 v14.83,46.94 20.12,46.94 v21.74,48.56
/IR0_EN  (via drill 0.61)
  Top 0.254: IC1.39 74.16,41.41 74.85,40.72 | 74.85,40.72 74.93,40.64 | v54.66,31.9 53.03,31.9 Q2.2 | v66.65,30.89 68.89,28.65 68.89,28.04 R1.1 | v72.95,30.68 72.95,31.5 74.37,32.92 74.37,40.23 74.85,40.72
  Bottom 0.254: v54.66,31.9 55.68,30.89 v66.65,30.89 68.07,29.46 71.73,29.46 v72.95,30.68
/IR1_EN  (via drill 0.61)
  Top 0.254: IC1.40 74.66,42.18 v74.98,41.86 | v50.39,30.89 49.38,31.9 Q4.2 | v56.29,30.07 58.73,30.07 | 58.73,30.07 58.73,28.04 R3.1 | v59.74,41.45 59.74,31.09 58.73,30.07
  Bottom 0.254: v50.39,30.89 51.21,30.07 v56.29,30.07 | v74.98,41.86 74.57,41.45 v59.74,41.45
/SERVO_ENABLE  (via drill 0.61)
  Top 0.254: IC1.22 64.08,51.38 57.15,44.45 v56.29,45.31 | 19.91,42.67 19.91,43.28 Q11.2 | 19.91,42.67 19.91,42.27 19.71,42.06 R34.2 | 19.91,42.67 v22.35,42.67
  Bottom 0.254: v22.35,42.67 23.57,43.89 54.86,43.89 v56.29,45.31
AGND  (via drill 0.61, 0.7)
  Top 0.254: IC1.93 71.16,61 v71.12,60.96 71.04,60.88 66.85,60.88 | 66.85,60.88 IC1.3 | 66.85,60.88 66.85,62.38 61.77,62.38 C10.2 61.57,62.38 61.37,62.59 61.37,69.7 61.98,70.31 61.98,71.12 C9.2 | v47.35,61.77 47.35,51.21 43.28,47.14 C14.2 | JP8.7 82.5,21.54 82.5,23.37 83.31,24.18 85.14,24.18 85.14,41.05 84.33,41.86 v84.33,46.33
  Top 0.61: v60.96,77.47 U$1.2
  Bottom 0.254: JP8.7 82.5,21.54 88.8,21.54 90.02,20.32 JP9.7 | v47.35,61.77 47.75,62.18 59.74,62.18 | v84.33,46.33 72.34,58.32 72.39,58.42 | 62.3,68.1 62.38,68.07 62.47,68.05
  Bottom 0.61: 60.96,67.31 v60.96,77.47
  pour Bottom (isolate 0.203): 59.69,68.58 72.39,68.58 72.39,58.42 59.69,58.42
BUMP_IN  (via drill 0.61, 0.7)
  Top 0.254: v81.48,38.2 81.48,42.88 v78.03,46.33 | IC1.5 69.66,59.88 73.66,55.88 v73.66,53.34
  Bottom 0.254: v81.48,38.2 78.84,35.56 JP22.1 | v78.03,46.33 73.36,51 73.36,53.03 v73.66,53.34
CANDLE_SENSE_0  (via drill 0.61)
  Top 0.254: IC1.97 69.16,66.73 68.58,67.31 62.23,67.31 v62.18,67.26 | v59.74,8.94 41.45,8.94 41.45,38 38.81,40.64 38.81,48.97 46.53,56.69 46.53,64.82 v47.35,65.63
  Bottom 0.254: v59.74,8.94 71.12,8.94 72.34,7.72 JP6.1 | v47.35,65.63 48.97,67.26 55.27,67.26 57.3,69.29 58.12,69.29 60.76,66.65 61.57,66.65 v62.18,67.26
CANDLE_SENSE_1  (via drill 0.61)
  Top 0.254: IC1.98 68.66,65.96 68.58,66.04 67.87,66.04 v67.87,66.45 | v75.18,69.49 76.61,70.92 76.61,74.17 80.26,77.83 80.26,78.44 80.47,78.64 94.89,78.64 94.89,66.45 99.57,61.77 99.57,9.55 93.88,3.86 93.88,1.63 93.47,1.22 79.86,1.22 v79.86,3.45
  Bottom 0.254: v67.87,66.45 70.92,69.49 v75.18,69.49 | v79.86,3.45 78.84,4.47 74.17,4.47 72.34,2.64 JP14.1
DEBUG_UART_RX  (via drill 0.61)
  Top 0.254: IC1.37 73.16,41.41 72.47,40.72 | 72.47,40.72 72.39,40.64 | v73.56,39.42 72.75,40.23 72.75,40.44 72.47,40.72
  Bottom 0.254: v73.56,39.42 73.97,39.01 91.85,39.01 95.3,35.56 JP13.4
DEBUG_UART_TX  (via drill 0.61)
  Top 0.254: IC1.38 73.66,40.64 v73.56,40.64 | v88.39,39.83 92.66,35.56 JP13.3
  Bottom 0.254: v73.56,40.64 74.37,39.83 v88.39,39.83
DGND  (via drill 0.61, 0.7)
  Top 0.254: IC1.43 76.16,49.57 v74.93,50.8 | IC1.33 71.16,49.57 v72.39,50.8 | v72.39,50.8 v74.93,50.8 | 67.26,50.88 IC1.23 | 67.26,50.88 72.31,50.88 | 72.31,50.88 v72.39,50.8 | IC1.13 v69.85,55.88 72.39,53.34 72.39,50.96 72.31,50.88 | v74.93,50.8 75.01,50.88 77.39,50.88 v77.47,50.8 | v78.74,55.88 IC1.63 | v78.74,55.88 v77.47,54.61 v77.47,50.8 | IC1.73 79.93,60.88 v78.74,59.69 | v78.74,55.88 v78.74,59.69 | IC1.84 75.66,62.77 v78.74,59.69 | IC1.53 77.55,50.88 v77.47,50.8 | 20.93,47.75 20.93,49.38 R27.1 20.93,49.58 20.93,52.02 R29.1 20.93,52.22 20.93,54.46 R25.1 | 20.93,47.75 20.93,47.14 R31.1 21.13,46.94 v21.13,43.89 | 28.85,44.3 26.82,44.3 C15.2 | 28.85,44.3 29.26,43.89 31.7,43.89 31.7,44.3 C13.2 | 20.93,47.75 22.55,47.75 22.55,49.78 22.35,49.99 22.35,51.61 25.2,54.46 29.06,54.46 29.06,54.25 | 29.06,54.25 29.06,45.31 28.85,45.11 28.85,44.3 | C20.1 11.18,3.86 11.18,6.3 C21.1 10.97,6.5 8.74,6.5 8.74,11.18 6.71,13.21 6.3,13.21 | 6.3,13.21 4.67,13.21 IC7.3 | 16.26,23.77 16.26,15.24 19.3,15.24 19.51,15.04 19.51,13.41 18.09,13.41 IC8.3 | 16.26,23.77 15.04,24.99 JP17.3 | 16.26,23.77 16.26,35.97 15.04,37.19 JP16.3 | 6.3,13.21 v6.3,13.61 | 50.8,55.88 49.58,55.88 49.58,58.32 JP3.2 | 50.8,55.88 C7.2 54.05,55.88 v55.27,54.66 | 50.8,55.88 50.8,67.26 49.58,68.48 JP3.10 | 80.06,11.58 79.25,11.58 79.25,13.82 R14.1 | 80.06,11.58 81.69,11.58 R32.1 | C3.2 85.14,55.27 85.95,56.08 v85.95,56.9 85.95,58.12 85.14,58.93 C2.2 85.14,59.13 85.14,61.57 C1.2 | C17.2 71.93,17.68 71.93,14.02 C18.2 72.14,13.82 74.78,11.18 74.78,7.72 JP6.2 | 89.2,12.8 89.2,13.82 R12.1 | 89.2,12.8 89.2,12.19 88.59,11.58 R33.2 | v66.04,38.81 67.06,38.81 C5.2
  Top 0.254: JP22.2 80.26,36.58 80.26,38.41 79.45,39.22 C4.2 | v74.37,68.48 74.37,67.46 C8.2 | 62.18,20.73 62.18,20.32 IC9.10 | 62.18,20.73 v62.18,21.34 | 89.2,12.8 85.75,12.8 85.75,9.55 JP4.2 83.72,7.52 83.72,6.3 80.87,6.3 80.06,7.11 80.06,11.58 | v61.37,37.19 61.77,37.59 61.77,43.89 67.26,49.38 67.26,50.88 | v57.51,42.47 54.05,42.47 54.05,45.72 C6.2 | 29.06,54.25 v29.46,54.25 | v57.3,25.6 62.18,20.73 | v10.57,40.44 10.57,41.05 9.75,41.86 R36.2
  Top 0.61: U$1.1 v63.5,76.2
  Bottom 0.254: v6.3,13.61 6.3,25.6 14.63,25.6 15.04,25.2 JP17.3 | 49.58,57.1 49.58,58.32 JP3.2 | v61.37,37.19 58.73,37.19 58.7,37.19 | 59.74,54.66 v55.27,54.66 54.86,54.25 v29.46,54.25 | 59.74,54.66 66.24,54.66 71.12,49.78 71.12,49.17 71.73,48.56 71.75,48.58 | 84.19,1.27 84.12,1.22 83.52,1.22 83.45,1.27 | 59.74,54.66 59.74,42.47 v57.51,42.47 | v57.3,25.6 54.46,25.6 48.16,31.9 44.3,31.9 44.3,35.97 44.7,36.37 48.26,36.37 | 11.18,39.83 13.61,37.39 14.83,37.39 JP16.3 | 11.18,39.83 v10.57,40.44 | 11.18,39.83 15.24,43.89 v21.13,43.89
  Bottom 0.61: v63.5,76.2 72.39,76.2 82.55,66.04
  pour Bottom (isolate 0.203): 73.66,74.93 73.66,57.15 48.26,57.15 48.26,1.27 99.06,1.27 99.06,74.93
ENC0_A  (via drill 0.61)
  Top 0.254: R27.2 19.51,49.58 17.27,49.58 R26.1 17.07,49.58 16.05,50.6 v16.05,50.8 | v12.19,51.61 11.38,50.8 11.38,17.88 9.75,16.26 9.75,14.22 10.57,13.41 11.18,13.41 IC7.12
  Bottom 0.254: v16.05,50.8 15.24,51.61 v12.19,51.61
ENC0_A_5V  (via drill 0.61)
  Top 0.254: v14.83,48.36 15.85,49.38 R26.2
  Bottom 0.254: v14.83,48.36 13.82,47.35 6.1,47.35 5.08,46.33 5.08,34.75 JP16.2
ENC0_B  (via drill 0.61)
  Top 0.254: R31.2 19.51,46.94 17.27,46.94 R30.1 17.07,47.14 16.05,48.16 v16.05,48.36 | v12.19,48.16 12.19,18.09 14.22,16.05 14.22,12.6 13.82,12.19 11.38,12.19 IC7.11
  Bottom 0.254: v16.05,48.36 15.24,49.17 13.21,49.17 v12.19,48.16
ENC0_B_5V
  Top 0.254: R30.2 16.05,46.94 16.05,44.7 15.85,44.5 15.24,44.5 15.24,40.03 15.04,39.83 JP16.4
ENC0_SEL  (via drill 0.61)
  Top 0.254: v3.25,19.51 3.25,12.19 4.47,12.19 IC7.4 | v72.14,49.38 72.14,47.95 IC1.35
  Bottom 0.254: v3.25,19.51 3.25,27.43 2.23,27.43 2.03,27.64 2.03,55.07 50.6,55.07 53.24,57.71 63.8,57.71 v72.14,49.38
ENC1_A  (via drill 0.61)
  Top 0.254: v17.07,55.88 17.07,54.66 R24.1 | v18.69,55.88 19.51,55.07 19.51,54.66 R25.2 | v33.53,55.88 33.53,20.52 29.46,16.46 29.46,13.21 24.79,13.21 IC8.12
  Bottom 0.254: v17.07,55.88 v18.69,55.88 v33.53,55.88
ENC1_A_5V  (via drill 0.61)
  Top 0.254: v14.83,53.44 15.85,54.46 R24.2 | v13.21,52.43 13.01,52.22 v13.01,24.79
  Bottom 0.254: v14.83,53.44 13.82,52.43 v13.21,52.43 | v13.01,24.79 15.04,22.76 JP17.2
ENC1_B  (via drill 0.61)
  Top 0.254: R28.1 17.27,52.02 v18.49,52.02 19.51,52.02 R29.2 | v25.6,53.65 26.01,54.05 28.65,54.05 28.65,46.53 27.64,45.52 24.79,45.52 24.79,38.61 24.38,38.2 24.38,18.49 22.15,16.26 22.15,14.02 23.98,12.19 24.59,12.19 IC8.11
  Bottom 0.254: v18.49,52.02 20.12,53.65 v25.6,53.65
ENC1_B_5V  (via drill 0.61)
  Top 0.254: v14.83,50.8 14.83,51 15.85,52.02 R28.2
  Bottom 0.254: v14.83,50.8 14.02,49.99 6.3,49.99 2.44,46.13 2.44,27.84 15.04,27.84 JP17.4
ENC1_SEL  (via drill 0.61)
  Top 0.254: IC1.36 72.66,42.18 71.12,40.64 72.14,39.62 72.14,30.28 v73.36,29.06 | v20.52,13.82 20.52,12.19 18.09,12.19 IC8.4
  Bottom 0.254: v20.52,13.82 20.93,14.22 47.14,14.22 61.98,29.06 v73.36,29.06
IR0_OUT  (via drill 0.61)
  Top 0.254: R14.2 80.87,14.02 84.12,14.02 R13.1 84.33,14.02 84.94,14.63 84.94,15.65 90.83,21.54 96.52,21.54 96.52,36.78 v88.39,44.91 | v70.31,62.38 70.1,62.59 70.1,63.8 IC1.95
  Bottom 0.254: v88.39,44.91 70.92,62.38 v70.31,62.38
IR1_OUT  (via drill 0.61)
  Top 0.254: IC1.96 69.66,67.5 68.58,68.58 62.59,68.58 | 62.59,68.58 62.23,68.58 | 95.91,16.26 93.27,16.26 91.03,14.02 R12.2 | 95.91,16.26 95.91,14.02 R11.2 | 95.91,16.26 99.16,19.51 99.16,61.57 94.08,66.65 v94.08,75.18 | v62.59,68.89 62.59,68.58
  Bottom 0.254: v94.08,75.18 92.05,77.22 63.2,77.22 62.59,76.61 v62.59,68.89
LED0
  Top 0.254: IC1.79 78.16,65.46 78.74,66.04 88.48,66.04 R37.1
LED1
  Top 0.254: IC1.80 77.66,66.23 78.74,67.31 85.94,67.31 R38.1
LED2
  Top 0.254: IC1.81 77.16,67 78.74,68.58 83.4,68.58 R39.1
LED3
  Top 0.254: IC1.82 76.66,67.77 78.74,69.85 80.86,69.85 R40.1
MOTOR0_DIR0  (via drill 0.61)
  Top 0.254: IC1.17 60.23,53.88 57.43,51.08 | 57.43,51.08 57.15,50.8 | v34.75,24.38 35.56,25.2 v35.56,47.75 | v57.51,51 57.43,51.08
  Bottom 0.254: v34.75,24.38 34.54,24.59 28.65,24.59 IC4.2 | v35.56,47.75 35.76,47.95 53.24,47.95 56.29,51 v57.51,51
MOTOR0_DIR1  (via drill 0.61)
  Top 0.254: IC1.18 61,53.38 57.45,49.84 | 57.45,49.84 57.15,49.53 | v57.51,49.78 57.45,49.84
  Bottom 0.254: v57.51,49.78 59.33,49.78 59.33,45.52 55.68,41.86 25.2,41.86 25.2,37.19 26.82,35.56 IC4.7
MOTOR0_N  (via drill 0.61)
  Top 0.254: v9.35,33.12 8.33,34.14 JP10.1
  Bottom 0.254: IC5.3 37.8,35.56 32.72,30.48 IC5.8 30.07,30.48 27.64,32.92 27.03,32.92 IC4.6 25.81,34.14 18.29,34.14 17.68,33.53 9.75,33.53 v9.35,33.12
MOTOR0_P  (via drill 0.61)
  Top 0.254: IC4.3 26.82,25.4 25.2,27.03 25.2,33.33 26.42,34.54 29.26,34.54 29.26,37.19 30.07,38 IC5.5 | v10.57,27.03 10.97,27.43 10.97,36.17 8.33,36.17 JP10.2
  Bottom 0.254: IC5.2 38,33.12 39.42,34.54 39.42,36.98 31.29,36.98 30.28,38 IC5.5 | v10.57,27.03 11.18,26.42 25.81,26.42 26.82,25.4 IC4.3
MOTOR0_PWM  (via drill 0.61)
  Top 0.254: IC1.15 58.69,54.88 57.15,53.34 57.1,53.24 56.69,52.83 56.69,48.97 v56.49,48.77 | v29.46,42.67 24.79,38 24.79,22.35 26.82,20.32 IC4.1
  Bottom 0.254: v29.46,42.67 29.87,43.08 56.29,43.08 58.93,45.72 58.93,48.77 v56.49,48.77
MOTOR1_DIR0  (via drill 0.61)
  Top 0.254: IC1.20 62.54,52.38 v57.71,47.55
  Bottom 0.254: IC4.10 24.79,41.05 24.79,43.48 56.08,43.48 58.52,45.92 58.52,47.55 v57.71,47.55
MOTOR1_DIR1  (via drill 0.61)
  Top 0.254: IC1.21 63.31,51.88 57.73,46.3 v57.71,46.33 | v23.98,45.52 23.98,27.64 19.3,22.96 IC4.15
  Bottom 0.254: v23.98,45.52 24.18,45.72 51.61,45.72 53.65,47.75 56.29,47.75 v57.71,46.33
MOTOR1_N  (via drill 0.61)
  Top 0.254: v10.36,21.34 8.33,23.37 JP11.1
  Bottom 0.254: IC6.3 37.59,23.57 35.15,23.57 30.28,18.69 IC6.8 30.07,18.69 26.01,18.69 23.37,21.34 | 23.37,21.34 IC4.14 | v10.36,21.34 23.37,21.34
MOTOR1_P  (via drill 0.61)
  Top 0.254: v9.75,28.65 9.75,26.82 8.33,25.4 JP11.2
  Bottom 0.254: 31.7,25.2 31.09,25.2 30.28,26.01 IC6.5 | 31.7,25.2 39.22,25.2 39.22,22.55 37.8,21.13 IC6.2 | 22.76,29.46 23.16,29.06 27.84,29.06 31.7,25.2 | 22.76,29.46 19.3,32.92 IC4.11 | v9.75,28.65 10.57,29.46 22.76,29.46
MOTOR1_PWM  (via drill 0.61)
  Top 0.254: IC1.16 59.46,54.38 v57.51,52.43 57.15,52.07 | v23.16,50.39 23.16,42.06 19.3,38.2 IC4.9
  Bottom 0.254: v23.16,50.39 25.2,52.43 v57.51,52.43
MOUSE0_SEL  (via drill 0.61)
  Top 0.254: IC1.25 65.12,49.88 58.52,43.28 58.52,38.41 v58.93,38 | v77.83,28.85 JP8.3
  Bottom 0.254: v77.83,28.85 68.68,38 v58.93,38
MOUSE1_SEL  (via drill 0.61)
  Top 0.254: 67.66,47.34 IC1.26 67.67,47.95 67.67,49.38 v70.31,49.38 | JP9.3 86.36,30.48 86.36,42.27 v85.14,43.48
  Bottom 0.254: v85.14,43.48 83.11,45.52 74.17,45.52 v70.31,49.38
N$1
  Top 0.254: JP1.1 10.57,71.32 11.58,72.34 11.58,73.76 11.79,73.97 22.55,73.97 22.55,71.32 JP2.2
N$2
  Top 0.254: IC2.IN 35.56,78.03 30.07,78.03 29.26,77.22 29.26,67.87 28.85,67.46 C19.+ 28.65,67.26 28.65,65.43 7.72,65.43 S1.1
N$3
  Top 0.254: LED1.C 44.5,65.63 44.5,61.98 R15.2
N$4  (via drill 0.61)
  Top 0.254: 86.36,2.64 89.81,2.64 LED3.A | v58.93,36.37 58.12,37.19 58.12,39.01 49.58,39.01 Q3.3 | v71.32,30.28 72.54,29.06 72.54,19.1 78.03,13.61 78.03,8.94 79.65,7.32 79.65,6.91 82.7,3.86 86.36,3.86 86.36,2.64 | 86.36,2.64 JP7.3
  Bottom 0.254: v58.93,36.37 59.13,36.17 63.6,36.17 69.49,30.28 v71.32,30.28
N$5
  Top 0.254: Q3.1 48.56,36.98 48.56,34.34 48.36,34.14 Q4.3 48.36,33.93 48.36,33.33 51.21,33.33 51.82,32.72 51.82,29.87 53.65,28.04 R4.1
N$6  (via drill 0.61)
  Top 0.254: v89.81,10.77 92.86,7.72 LED2.C | v82.7,9.96 83.31,10.57 83.31,11.38 R32.2
  Bottom 0.254: v89.81,10.77 89,9.96 v82.7,9.96
N$7
  Top 0.254: 6.1,67.46 3.86,69.7 JP23.2 | 6.1,67.46 6.1,59.94 S1.2 | 6.1,67.46 9.96,67.46 11.38,68.89 11.38,70.1 12.39,71.12 JP1.2
N$8  (via drill 0.61)
  Top 0.254: LED2.A 89.81,7.72 86.36,7.72 JP4.3 | v43.48,40.44 43.48,40.03 44.3,39.22 Q1.3 | v41.86,38.81 42.27,38.41 42.27,27.43 49.58,20.12 60.55,20.12 60.55,3.66 62.99,1.22 79.05,1.22 v79.05,5.28
  Bottom 0.254: v41.86,38.81 v43.48,40.44 | v79.05,5.28 79.45,5.69 84.73,5.69 86.36,7.32 JP4.3
N$9  (via drill 0.61)
  Top 0.254: v49.38,34.14 52.02,34.14 Q2.3 | v45.11,35.56 43.69,36.98 Q1.1 | v61.37,32.92 62.79,32.92 63.2,32.51 63.2,28.65 63.8,28.04 R2.1
  Bottom 0.254: v45.11,35.56 47.95,35.56 v49.38,34.14 60.15,34.14 v61.37,32.92
N$10
  Top 0.254: LED3.C 92.86,2.64 90.83,4.67 90.83,8.53 89,10.36 86.97,10.36 86.97,11.38 R33.1
N$11  (via drill 0.61)
  Top 0.254: 42.67,33.93 44.3,33.93 Q5.3 | 42.67,33.93 42.67,28.85 43.48,28.04 R6.1 | 42.67,33.93 42.67,41.25 44.91,43.48 44.91,47.55 v46.13,48.77
  Bottom 0.254: v46.13,48.77 45.31,49.58 7.72,49.58 3.86,45.72 JP12.1
N$12  (via drill 0.61)
  Top 0.254: v30.28,12.8 30.28,13.82 R8.2 | v13.41,13.01 11.99,14.43 11.38,14.43 IC7.13
  Bottom 0.254: v30.28,12.8 30.07,13.01 v13.41,13.01
N$13
  Top 0.254: LED4.C 5.49,41.86 7.92,41.86 R36.1
N$14  (via drill 0.61)
  Top 0.254: Q11.3 19.1,45.72 20.32,45.72 20.32,52.63 17.88,55.07 17.88,56.29 17.48,56.69 14.02,56.69 14.02,43.69 14.22,43.48 Q12.1 14.43,43.28 v14.43,41.86 | v19.1,39.42 19.1,40.23 19.51,40.64 R35.2
  Bottom 0.254: v19.1,39.42 16.66,41.86 v14.43,41.86
N$15  (via drill 0.61)
  Top 0.254: v34.75,15.24 34.75,14.43 35.15,14.02 R10.2 | v26.42,15.04 24.79,15.04 24.79,14.63 IC8.13
  Bottom 0.254: v34.75,15.24 34.54,15.04 v26.42,15.04
N$16  (via drill 0.61)
  Top 0.254: v91.64,10.36 91.64,11.18 94.28,13.82 R11.1
  Bottom 0.254: v91.64,10.36 85.75,4.47 82.91,4.47 81.28,2.85 JP7.1
N$18
  Top 0.254: R13.2 85.75,13.82 85.34,13.41 85.34,11.38 81.69,7.72 81.28,7.72 JP4.1
N$20
  Top 0.254: R40.2 LED8.C
N$21
  Top 0.254: LED7.C 85.14,74.57 85.14,72.14 R39.2
N$22
  Top 0.254: LED5.C 92.66,74.57 92.66,72.14 R37.2
N$23
  Top 0.254: LED6.C 89,74.57 89,72.14 R38.2
NCTS  (via drill 0.61)
  Top 0.254: IC1.42 75.66,43.72 78.69,40.69 | 78.69,40.69 78.74,40.64 | v58.93,19.3 58.93,18.29 43.28,18.29 IC9.12 | v74.98,27.23 76.2,28.45 76.2,38.2 78.69,40.69
  Bottom 0.254: v58.93,19.3 66.85,27.23 v74.98,27.23
NRTS  (via drill 0.61)
  Top 0.254: IC1.41 75.16,42.95 77.44,40.66 | 77.44,40.66 77.47,40.64 | v59.74,12.8 59.74,10.16 IC9.16 | v73.36,26.42 74.17,27.23 74.17,32.11 75.79,33.73 75.79,39.01 77.44,40.66
  Bottom 0.254: v59.74,12.8 v73.36,26.42
NSRST  (via drill 0.61)
  Top 0.254: IC1.90 72.66,68.31 68.58,72.39 62.23,72.39 62.18,72.34 61.57,72.34 v57.71,68.48
  Bottom 0.254: v57.71,68.48 54.05,64.82 50.8,64.82 49.58,63.6 JP3.6
PE  (via drill 0.61, 0.7)
  Top 0.254: IC5.6 30.28,35.56 30.28,33.12 IC5.7 30.07,32.92 27.03,29.87 | IC6.7 30.28,21.13 30.28,23.57 IC6.6 30.07,23.77 28.65,25.2 28.65,26.21 IC4.4 27.03,28.04 27.03,29.87 | IC4.13 IC4.12 | 27.03,29.87 27.03,30.48 IC4.5 27.03,29.87 | C24.- 24.59,59.74 24.59,62.18 19.51,62.18 v18.69,61.37 17.07,59.74 C16.- 16.87,59.54 16.26,59.54 10.97,54.25 10.97,47.75 8.94,45.72 JP12.3 | C19.- 24.59,67.46 v22.55,67.46 20.73,67.46 20.73,71.12 JP2.1 | C12.- 33.53,59.74 33.53,67.26 C11.- 33.33,67.46 33.12,67.67 33.12,76.2 IC2.GND | IC3.GND 43.28,73.76 43.28,61.16 44.3,60.15 R15.1 | JP5.1 72.54,72.54 69.09,72.54 66.45,75.18 55.68,75.18 55.68,76.61 U$1.3
  Top 0.61: U$1.3 52.7,76.83 50.8,78.74 40.64,78.74 v39.37,77.47
  Bottom 0.254: IC4.13 19.3,28.04 26.82,28.04 IC4.4 | IC5.6 30.07,35.56 29.06,34.54 17.07,34.54 15.65,35.97 13.82,35.97 8.94,40.84 8.94,45.72 JP12.3
  pour Bottom (isolate 0.203): 46.99,78.74 46.99,57.15 1.27,57.15 1.27,78.74
SERVO_PWM  (via drill 0.61)
  Top 0.254: IC1.19 61.77,52.88 57.15,48.26 57.1,48.16 56.9,47.95 56.9,47.55 v56.08,46.74 | v45.31,30.07 45.31,31.9 Q5.2 | R5.1 48.56,28.04 48.56,28.85 v47.95,29.46 48.16,29.67 48.16,32.92 47.55,33.53 47.55,39.01 v53.24,44.7
  Bottom 0.254: v45.31,30.07 45.92,29.46 v47.95,29.46 | v53.24,44.7 55.27,46.74 v56.08,46.74
SPI_CLK  (via drill 0.61)
  Top 0.254: IC1.32 70.66,43.99 70.03,43.36 v70.1,43.28 | v7.92,10.77 4.67,10.77 IC7.5 | v16.26,10.77 17.88,10.77 IC8.5 | 85.55,22.96 90.22,22.96 90.22,23.37 91.03,24.18 93.88,24.18 93.88,22.96 JP9.6 | 85.55,22.96 83.92,22.96 JP8.6 | v85.14,42.27 85.55,41.86 85.55,22.96
  Bottom 0.254: v7.92,10.77 v16.26,10.77 17.48,11.99 67.87,11.99 80.06,24.18 82.5,24.18 JP8.6 | v70.1,43.28 70.71,42.67 84.73,42.67 v85.14,42.27
SPI_MISO  (via drill 0.61)
  Top 0.254: IC1.31 70.16,44.76 66.24,40.84 | 66.24,40.84 66.04,40.64 | v7.92,9.55 4.67,9.55 IC7.6 | v16.26,9.55 17.88,9.55 IC8.6 | JP9.5 91.44,22.76 87.78,19.1 80.67,19.1 80.06,19.71 80.06,21.54 81.28,22.76 JP8.5 81.28,22.96 77.01,27.23 v77.01,30.89 | v67.26,39.83 66.24,40.84
  Bottom 0.254: v7.92,9.55 v16.26,9.55 18.29,11.58 69.7,11.58 80.87,22.76 81.28,22.76 JP8.5 | v67.26,39.83 68.68,38.41 69.49,38.41 v77.01,30.89
SPI_MOSI  (via drill 0.61)
  Top 0.254: IC1.30 69.66,45.53 65,40.87 | 65,40.87 64.77,40.64 | v7.92,8.33 4.67,8.33 IC7.7 | v16.26,8.33 17.88,8.33 IC8.7 | v77.01,33.93 82.5,28.45 82.5,26.62 83.72,25.4 JP8.4 | v65.23,40.64 65,40.87
  Bottom 0.254: v16.26,8.33 v7.92,8.33 7.11,9.14 7.11,17.48 35.36,17.48 38,20.12 38.2,20.12 43.08,24.99 43.08,39.42 64.01,39.42 v65.23,40.64 70.31,40.64 v77.01,33.93 | JP8.4 83.92,25.4 85.14,26.62 92.66,26.62 93.88,25.4 JP9.4
SPICOMM_CLK  (via drill 0.61)
  Top 0.254: IC1.52 83.4,50.38 85.09,52.07 85.14,52.02 85.14,52.22 v85.75,52.83 | Q10.3 92.66,64.62 89.61,64.62 R23.2 89.41,64.82 88.59,65.63 87.17,65.63 v87.17,55.27
  Bottom 0.254: v87.17,55.27 85.75,53.85 v85.75,52.83
SPICOMM_CLK_BEAGLE
  Top 0.254: 93.47,60.96 93.47,62.38 Q10.2 | 93.47,60.96 97.74,60.96 97.74,59.74 JP21.6 | R22.2 93.47,60.96
SPICOMM_CS  (via drill 0.61)
  Top 0.254: IC1.49 79.16,46.57 80.01,45.72 82.55,45.72 85.09,48.26 85.14,48.36 85.14,48.77 v87.17,48.77 | v92.66,48.16 92.66,49.17 Q9.3 | v91.03,48.36 89.61,48.36 89.61,49.38 R21.2
  Bottom 0.254: v92.66,48.16 92.46,48.36 v91.03,48.36 90.63,48.77 v87.17,48.77
SPICOMM_CS_BEAGLE
  Top 0.254: R20.2 93.47,45.72 93.47,47.14 Q9.2 93.67,47.35 97.74,51.41 97.74,52.02 JP21.3
SPICOMM_MISO  (via drill 0.61)
  Top 0.254: IC1.51 84.17,49.88 85.09,50.8 85.14,50.8 87.38,53.03 v87.38,53.44 | v91.03,59.54 89.61,59.54 R17.2 | v92.66,58.32 92.66,59.33 Q7.3
  Bottom 0.254: 92.25,58.32 v91.03,59.54 | v87.38,53.44 92.25,58.32 | 92.25,58.32 v92.66,58.32
SPICOMM_MISO_BEAGLE
  Top 0.254: R16.2 93.47,55.88 93.47,57.3 Q7.2 93.67,57.3 97.74,57.3 JP21.5
SPICOMM_MOSI  (via drill 0.61)
  Top 0.254: IC1.50 83.44,47.88 v87.58,52.02 | v91.03,54.46 89.61,54.46 R19.2 | v92.66,53.24 92.66,54.25 Q8.3
  Bottom 0.254: v92.66,53.24 92.25,53.24 v91.03,54.46 88.59,52.02 v87.58,52.02
SPICOMM_MOSI_BEAGLE
  Top 0.254: R18.2 93.47,50.8 93.47,52.22 Q8.2 93.67,52.43 96.52,52.43 96.52,53.24 97.74,54.46 JP21.4
TCK  (via drill 0.61)
  Top 0.254: IC1.11 57.42,56.88 57.15,57.15 57.1,57.1 57.1,57.3 v55.88,58.52
  Bottom 0.254: v55.88,58.52 52.22,58.52 JP3.1
TDI
  Top 0.254: IC1.10 58.19,57.38 57.15,58.42 57.1,58.52 57.1,58.93 55.88,60.15 55.88,64.82 52.22,68.48 JP3.9
TDO
  Top 0.254: IC1.12 57.65,56.38 57.15,55.88 57.1,55.88 57.1,56.08 52.22,60.96 JP3.3
TMS  (via drill 0.61)
  Top 0.254: IC1.9 58.96,57.88 56.69,60.15 v56.69,62.99
  Bottom 0.254: v56.69,62.99 52.63,62.99 52.22,63.4 JP3.5
XBEE_RX  (via drill 0.61)
  Top 0.254: IC1.27 68.16,46.57 62.31,40.72 | 62.31,40.72 62.23,40.64 | v62.38,32.11 62.38,27.64 63.6,26.42 63.6,5.69 62.18,4.27 IC9.2 | v62.38,35.36 62.38,40.64 62.31,40.72
  Bottom 0.254: v62.38,32.11 v62.38,35.36
XBEE_TX  (via drill 0.61)
  Top 0.254: IC1.28 68.66,45.8 63.55,40.69 | 63.55,40.69 63.5,40.64 | v65.84,35.15 65.84,30.48 67.87,28.45 67.87,8.94 65.23,6.3 IC9.3 | v64.62,36.37 63.6,37.39 63.6,40.64 63.55,40.69
  Bottom 0.254: v65.84,35.15 v64.62,36.37
XTALI  (via drill 0.61)
  Top 0.254: 14.83,5.89 R7.1 | 14.83,5.89 14.83,6.3 12.39,6.3 C21.2 12.19,6.5 12.19,7.11 10.57,7.11 9.35,8.33 9.35,14.43 4.67,14.43 IC7.2 | 14.83,5.89 15.44,5.89 | 15.44,5.89 16.66,5.89 16.87,5.69 16.87,5.08 R9.1 20.12,5.08 20.12,6.5 v20.52,6.91 | 15.44,5.89 15.44,14.43 17.88,14.43 IC8.2
  Bottom 0.254: v20.52,6.91 33.12,6.91 34.14,5.89 Q6.1
XTALO  (via drill 0.61)
  Top 0.254: 16.05,4.27 16.05,5.08 R7.2 | 16.05,4.27 16.05,3.86 12.39,3.86 C20.2 | 16.05,4.27 20.32,4.27 21.13,5.08 R9.2 21.34,5.08 21.34,5.89 | 21.34,5.89 21.34,15.85 18.09,15.85 IC8.1 | v4.67,16.87 4.67,16.05 IC7.1 | 21.34,5.89 29.06,5.89 Q6.2
  Bottom 0.254: v4.67,16.87 4.67,6.5 19.71,6.5 20.32,5.89 29.06,5.89 Q6.2

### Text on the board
tPlace: 3 | 2 | 1 | 0 | - | Ext | + | 5V Expansion | JTAG | 1 | SERVO | 1 | 1 | BUMP | Tx | Rx | MOTOR0 | MOTOR1 | MOUSE0 | MOUSE1 | 1 | 1 | IR0 | IR1 | MobileBoard Rev B | CANDLE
